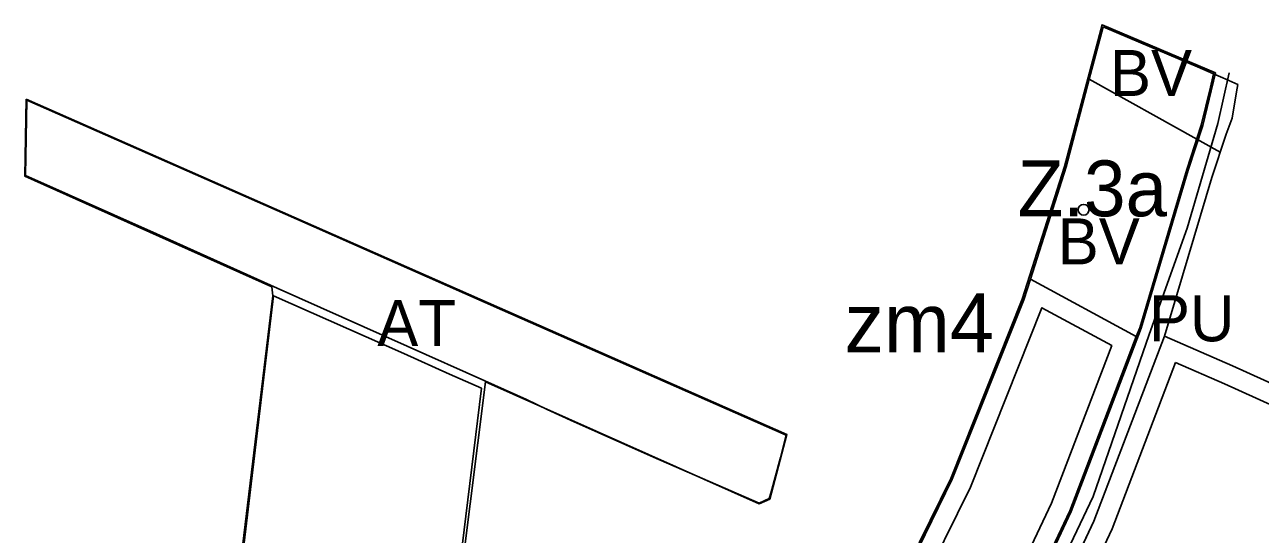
# Model space of a CAD drawing. Extents: x -555070 to -553076, y -1186731 to -1182766.
# Drawn here: x -555035.2 to -554659.4, y -1185196 to -1185040.9 of the extents above; entities that cross this region are included whole.
import ezdxf

# ---------------------------------------------------------------- set-up
doc = ezdxf.new("R2010")
doc.units = 0
for name, color, linetype in [('HRANICE_ZMENY_DO_KOO', 7, 'Continuous'), ('Level 10', 7, 'Continuous'), ('Level 13', 7, 'Continuous'), ('Level 4', 7, 'Continuous'), ('Level 46', 7, 'Continuous'), ('Level 52', 7, 'Continuous'), ('Level 56', 7, 'Continuous'), ('Level 59', 7, 'Continuous'), ('Level 6', 7, 'Continuous'), ('Level 63', 7, 'Continuous'), ('navrh_BV', 7, 'Continuous'), ('OBRYS_PLOCH', 7, 'Continuous'), ('rezerva_BV', 7, 'Continuous'), ('stav_AT', 7, 'Continuous'), ('stav_BV', 7, 'Continuous'), ('stav_PU', 7, 'Continuous'), ('ZU_plocha_aktualizace', 7, 'Continuous')]:
    doc.layers.add(name, color=color, linetype=linetype)

msp = doc.modelspace()

# ---------------------------------------------------------------- linework, layer by layer
at = {"layer": 'HRANICE_ZMENY_DO_KOO'}
msp.add_lwpolyline([(-554781.14, -1185319.16), (-554749.64, -1185258.53), (-554735.45, -1185228.43), (-554735.94, -1185228.17), (-554732.88, -1185222.18), (-554722.28, -1185200.47), (-554716.89, -1185189.03), (-554695.6, -1185133.26), (-554681.28, -1185085.12), (-554676.85, -1185071.58), (-554673.03, -1185055.54), (-554678.3, -1185053.24), (-554698.85, -1185044.53), (-554707.52, -1185040.87), (-554718.97, -1185084), (-554731.8, -1185124.46), (-554753.51, -1185179), (-554769.31, -1185211.12), (-554783.7, -1185241.67), (-554814.38, -1185300.72)], dxfattribs=at)
msp.add_lwpolyline([(-555034.79, -1185063.53), (-555035.23, -1185086.95), (-554960.01, -1185120.64), (-554959.71, -1185123.38), (-554985.4, -1185335.61), (-554942.05, -1185324.03), (-554915.83, -1185315.05), (-554895.09, -1185149.59), (-554811.81, -1185186.74), (-554808.6, -1185185.28), (-554803.37, -1185165.66)], close=True, dxfattribs=at)
at = {"layer": 'Level 13'}
for p, q in [((-554707.18, -1185041.55), (-554711.41, -1185057.49)), ((-554673.61, -1185055.83), (-554678.5, -1185053.7)), ((-554711.41, -1185057.49), (-554718.48, -1185084.14)), ((-554674.57, -1185059.86), (-554673.61, -1185055.83)), ((-554677.33, -1185071.44), (-554674.57, -1185059.86)), ((-554678.65, -1185075.47), (-554677.33, -1185071.44)), ((-554681.76, -1185084.97), (-554679.31, -1185077.48)), ((-554679.31, -1185077.48), (-554678.73, -1185075.72)), ((-554678.73, -1185075.72), (-554678.65, -1185075.47)), ((-554718.48, -1185084.14), (-554729.32, -1185118.29)), ((-554696.07, -1185133.1), (-554681.76, -1185084.97)), ((-554729.32, -1185118.29), (-554731.33, -1185124.63)), ((-554731.33, -1185124.63), (-554753.06, -1185179.2)), ((-554697.1, -1185135.79), (-554696.07, -1185133.1)), ((-554717.35, -1185188.83), (-554697.1, -1185135.79)), ((-554688.49, -1185135.67), (-554709.98, -1185191.97)), ((-554667.86, -1185144.71), (-554688.49, -1185135.67)), ((-554652.87, -1185151.49), (-554667.86, -1185144.71)), ((-554753.06, -1185179.2), (-554768.86, -1185211.34)), ((-554722.73, -1185200.26), (-554717.35, -1185188.83)), ((-554709.98, -1185191.97), (-554738.91, -1185253.34))]:
    msp.add_line(p, q, dxfattribs=at)
msp.add_lwpolyline([(-554678.5, -1185053.7), (-554699.04, -1185044.99), (-554707.18, -1185041.55)], dxfattribs=at)
at = {"layer": 'Level 4'}
msp.add_circle((-554713.12, -1185097.19), 1.64, dxfattribs=at)
at = {"layer": 'Level 52'}
msp.add_lwpolyline([(-554707.18, -1185041.55), (-554711.41, -1185057.49), (-554678.73, -1185075.72), (-554671.61, -1185079.7)], dxfattribs=at)
at = {"layer": 'Level 56'}
for p, q in [((-554711.41, -1185057.49), (-554718.48, -1185084.14)), ((-554711.41, -1185057.49), (-554678.73, -1185075.72)), ((-554681.76, -1185084.97), (-554679.31, -1185077.48)), ((-554679.31, -1185077.48), (-554678.65, -1185075.47)), ((-554718.48, -1185084.14), (-554729.32, -1185118.29)), ((-554696.07, -1185133.1), (-554681.76, -1185084.97)), ((-554729.32, -1185118.29), (-554697.1, -1185135.79)), ((-554697.1, -1185135.79), (-554696.07, -1185133.1))]:
    msp.add_line(p, q, dxfattribs=at)
at = {"layer": 'Level 6'}
msp.add_lwpolyline([(-554731.38, -1185228.54), (-554728.11, -1185222.01), (-554710.22, -1185184.49), (-554693.2, -1185135.17), (-554681.62, -1185102.76), (-554672.29, -1185070.96), (-554668.89, -1185055.54)], dxfattribs=at)
at = {"layer": 'navrh_BV'}
for p, q in [((-554711.41, -1185057.49), (-554718.48, -1185084.14)), ((-554678.73, -1185075.72), (-554711.41, -1185057.49)), ((-554681.76, -1185084.97), (-554679.31, -1185077.48)), ((-554679.31, -1185077.48), (-554678.73, -1185075.72)), ((-554718.48, -1185084.14), (-554729.32, -1185118.29)), ((-554696.07, -1185133.1), (-554681.76, -1185084.97)), ((-554729.32, -1185118.29), (-554697.1, -1185135.79)), ((-554697.1, -1185135.79), (-554696.07, -1185133.1))]:
    msp.add_line(p, q, dxfattribs=at)
at = {"layer": 'OBRYS_PLOCH'}
for p, q in [((-554707.18, -1185041.55), (-554711.41, -1185057.49)), ((-554673.61, -1185055.83), (-554678.5, -1185053.7)), ((-554711.41, -1185057.49), (-554678.73, -1185075.72)), ((-554673.61, -1185055.83), (-554674.57, -1185059.86)), ((-554674.57, -1185059.86), (-554673.61, -1185055.83)), ((-554670.81, -1185057.05), (-554673.61, -1185055.83)), ((-554670.81, -1185057.05), (-554673.61, -1185055.83)), ((-554666.18, -1185059.07), (-554670.81, -1185057.05)), ((-554666.18, -1185059.07), (-554670.81, -1185057.05)), ((-554674.57, -1185059.86), (-554677.33, -1185071.44)), ((-554677.33, -1185071.44), (-554674.57, -1185059.86)), ((-554667.89, -1185069.33), (-554666.61, -1185061.26)), ((-554666.61, -1185061.26), (-554666.18, -1185059.07)), ((-554666.61, -1185061.26), (-554666.18, -1185059.07)), ((-554669.8, -1185074.16), (-554667.89, -1185069.33)), ((-554677.33, -1185071.44), (-554679.31, -1185077.48)), ((-554677.33, -1185071.44), (-554679.31, -1185077.48)), ((-554678.65, -1185075.47), (-554677.33, -1185071.44)), ((-554679.31, -1185077.48), (-554681.76, -1185084.97)), ((-554679.31, -1185077.48), (-554681.76, -1185084.97)), ((-554678.73, -1185075.72), (-554678.65, -1185075.47)), ((-554674.12, -1185087.36), (-554669.8, -1185074.16)), ((-554674.12, -1185087.36), (-554669.8, -1185074.16)), ((-554681.76, -1185084.97), (-554696.07, -1185133.1)), ((-554681.76, -1185084.97), (-554696.07, -1185133.1)), ((-554688.49, -1185135.67), (-554674.12, -1185087.36)), ((-554688.49, -1185135.67), (-554674.12, -1185087.36)), ((-554959.51, -1185123.38), (-554968.49, -1185198.61)), ((-554919.89, -1185140.98), (-554959.51, -1185123.38)), ((-554696.07, -1185133.1), (-554717.35, -1185188.83)), ((-554696.07, -1185133.1), (-554717.35, -1185188.83)), ((-554709.98, -1185191.97), (-554688.49, -1185135.67)), ((-554709.98, -1185191.97), (-554688.49, -1185135.67)), ((-554905.97, -1185147.2), (-554919.89, -1185140.98)), ((-554896.25, -1185151.54), (-554905.97, -1185147.2)), ((-554905.64, -1185227.88), (-554896.25, -1185151.54)), ((-554717.35, -1185188.83), (-554722.73, -1185200.26)), ((-554717.35, -1185188.83), (-554722.73, -1185200.26)), ((-554738.91, -1185253.34), (-554709.98, -1185191.97)), ((-554738.91, -1185253.34), (-554709.98, -1185191.97))]:
    msp.add_line(p, q, dxfattribs=at)
for points in [[(-554678.5, -1185053.7), (-554699.04, -1185044.99), (-554707.18, -1185041.55)], [(-554673.61, -1185055.83), (-554674.57, -1185059.86), (-554677.33, -1185071.44)], [(-554669.8, -1185074.16), (-554667.89, -1185069.33), (-554666.61, -1185061.26)]]:
    msp.add_lwpolyline(points, dxfattribs=at)
at = {"layer": 'rezerva_BV'}
for p, q in [((-554729.32, -1185118.29), (-554731.33, -1185124.63)), ((-554729.32, -1185118.29), (-554731.33, -1185124.63)), ((-554697.1, -1185135.79), (-554729.32, -1185118.29)), ((-554697.1, -1185135.79), (-554729.32, -1185118.29)), ((-554731.33, -1185124.63), (-554753.06, -1185179.2)), ((-554731.33, -1185124.63), (-554753.06, -1185179.2)), ((-554717.35, -1185188.83), (-554697.1, -1185135.79)), ((-554717.35, -1185188.83), (-554697.1, -1185135.79)), ((-554688.49, -1185135.67), (-554709.98, -1185191.97)), ((-554688.49, -1185135.67), (-554709.98, -1185191.97)), ((-554667.86, -1185144.71), (-554688.49, -1185135.67)), ((-554667.86, -1185144.71), (-554688.49, -1185135.67)), ((-554704.46, -1185194.32), (-554685.13, -1185143.69)), ((-554685.13, -1185143.69), (-554670.3, -1185150.19)), ((-554652.87, -1185151.49), (-554667.86, -1185144.71)), ((-554652.87, -1185151.49), (-554667.86, -1185144.71)), ((-554670.3, -1185150.19), (-554655.3, -1185156.98)), ((-554753.06, -1185179.2), (-554768.86, -1185211.34)), ((-554753.06, -1185179.2), (-554768.86, -1185211.34)), ((-554722.73, -1185200.26), (-554717.35, -1185188.83)), ((-554722.73, -1185200.26), (-554717.35, -1185188.83)), ((-554709.98, -1185191.97), (-554738.91, -1185253.34)), ((-554709.98, -1185191.97), (-554738.91, -1185253.34))]:
    msp.add_line(p, q, dxfattribs=at)
for points in [[(-554755.47, -1185255.65), (-554783.85, -1185310.28), (-554805.8, -1185298.3), (-554777.88, -1185244.55), (-554763.45, -1185213.94), (-554747.57, -1185181.64), (-554725.82, -1185127.02), (-554704.58, -1185138.55), (-554722.87, -1185186.48), (-554728.14, -1185197.66), (-554738.8, -1185219.49), (-554741.6, -1185226.21), (-554755.47, -1185255.65)], [(-554766.29, -1185319.86), (-554737.54, -1185264.52), (-554704.46, -1185194.32)]]:
    msp.add_lwpolyline(points, dxfattribs=at)
at = {"layer": 'stav_AT'}
for p, q in [((-554959.51, -1185123.38), (-554968.49, -1185198.61)), ((-554919.89, -1185140.98), (-554959.51, -1185123.38)), ((-554905.97, -1185147.2), (-554919.89, -1185140.98)), ((-554896.25, -1185151.54), (-554905.97, -1185147.2)), ((-554905.64, -1185227.88), (-554896.25, -1185151.54))]:
    msp.add_line(p, q, dxfattribs=at)
for points in [[(-555034.6, -1185063.83), (-555035.03, -1185086.82), (-554995.14, -1185104.5), (-554958.47, -1185121.11), (-554918.85, -1185138.71), (-554895.25, -1185149.3), (-554882.6, -1185154.99), (-554876.27, -1185158.01), (-554869.18, -1185161.26), (-554843.98, -1185172.48)], [(-554952.46, -1185100.05), (-555034.6, -1185063.83)], [(-554889.9, -1185127.79), (-554952.46, -1185100.05)], [(-554843.98, -1185172.48), (-554811.81, -1185186.52), (-554808.77, -1185185.14), (-554808.23, -1185183.43), (-554805.28, -1185172.63), (-554803.61, -1185165.77), (-554866.89, -1185137.92), (-554889.9, -1185127.79)]]:
    msp.add_lwpolyline(points, dxfattribs=at)
at = {"layer": 'stav_BV'}
for p, q in [((-554707.18, -1185041.55), (-554711.41, -1185057.49)), ((-554673.61, -1185055.83), (-554678.5, -1185053.7)), ((-554711.41, -1185057.49), (-554678.73, -1185075.72)), ((-554674.57, -1185059.86), (-554673.61, -1185055.83)), ((-554677.33, -1185071.44), (-554674.57, -1185059.86)), ((-554678.65, -1185075.47), (-554677.33, -1185071.44)), ((-554678.73, -1185075.72), (-554678.65, -1185075.47))]:
    msp.add_line(p, q, dxfattribs=at)
msp.add_lwpolyline([(-554678.5, -1185053.7), (-554699.04, -1185044.99), (-554707.18, -1185041.55)], dxfattribs=at)
at = {"layer": 'stav_PU'}
for p, q in [((-554673.61, -1185055.83), (-554674.57, -1185059.86)), ((-554670.81, -1185057.05), (-554673.61, -1185055.83)), ((-554670.81, -1185057.05), (-554673.61, -1185055.83)), ((-554666.18, -1185059.07), (-554670.81, -1185057.05)), ((-554666.18, -1185059.07), (-554670.81, -1185057.05)), ((-554674.57, -1185059.86), (-554677.33, -1185071.44)), ((-554666.61, -1185061.26), (-554666.18, -1185059.07)), ((-554666.61, -1185061.26), (-554666.18, -1185059.07)), ((-554677.33, -1185071.44), (-554679.31, -1185077.48)), ((-554679.31, -1185077.48), (-554681.76, -1185084.97)), ((-554679.31, -1185077.48), (-554681.76, -1185084.97)), ((-554674.12, -1185087.36), (-554669.8, -1185074.16)), ((-554674.12, -1185087.36), (-554669.8, -1185074.16)), ((-554681.76, -1185084.97), (-554696.07, -1185133.1)), ((-554688.49, -1185135.67), (-554674.12, -1185087.36)), ((-554688.49, -1185135.67), (-554674.12, -1185087.36)), ((-554696.07, -1185133.1), (-554717.35, -1185188.83)), ((-554709.98, -1185191.97), (-554688.49, -1185135.67)), ((-554717.35, -1185188.83), (-554722.73, -1185200.26)), ((-554717.35, -1185188.83), (-554722.73, -1185200.26)), ((-554738.91, -1185253.34), (-554709.98, -1185191.97))]:
    msp.add_line(p, q, dxfattribs=at)
for points in [[(-554673.61, -1185055.83), (-554674.57, -1185059.86), (-554677.33, -1185071.44), (-554679.31, -1185077.48)], [(-554669.8, -1185074.16), (-554667.89, -1185069.33), (-554666.61, -1185061.26)], [(-554669.8, -1185074.16), (-554667.89, -1185069.33), (-554666.61, -1185061.26)], [(-554681.76, -1185084.97), (-554696.07, -1185133.1), (-554717.35, -1185188.83)], [(-554738.91, -1185253.34), (-554709.98, -1185191.97), (-554688.49, -1185135.67)]]:
    msp.add_lwpolyline(points, dxfattribs=at)
at = {"layer": 'ZU_plocha_aktualizace'}
for p, q in [((-554707.18, -1185041.55), (-554711.41, -1185057.49)), ((-554707.18, -1185041.55), (-554711.41, -1185057.49)), ((-554673.61, -1185055.83), (-554678.5, -1185053.7)), ((-554673.61, -1185055.83), (-554678.5, -1185053.7)), ((-554711.41, -1185057.49), (-554678.73, -1185075.72)), ((-554711.41, -1185057.49), (-554678.73, -1185075.72)), ((-554674.57, -1185059.86), (-554673.61, -1185055.83)), ((-554673.61, -1185055.83), (-554674.57, -1185059.86)), ((-554674.57, -1185059.86), (-554673.61, -1185055.83)), ((-554673.61, -1185055.83), (-554674.57, -1185059.86)), ((-554670.81, -1185057.05), (-554673.61, -1185055.83)), ((-554670.81, -1185057.05), (-554673.61, -1185055.83)), ((-554666.18, -1185059.07), (-554670.81, -1185057.05)), ((-554666.18, -1185059.07), (-554670.81, -1185057.05)), ((-554677.33, -1185071.44), (-554674.57, -1185059.86)), ((-554674.57, -1185059.86), (-554677.33, -1185071.44)), ((-554677.33, -1185071.44), (-554674.57, -1185059.86)), ((-554674.57, -1185059.86), (-554677.33, -1185071.44)), ((-554667.89, -1185069.33), (-554666.61, -1185061.26)), ((-554666.61, -1185061.26), (-554666.18, -1185059.07)), ((-554666.61, -1185061.26), (-554666.18, -1185059.07)), ((-554669.8, -1185074.16), (-554667.89, -1185069.33)), ((-554678.65, -1185075.47), (-554677.33, -1185071.44)), ((-554677.33, -1185071.44), (-554678.65, -1185075.47)), ((-554678.65, -1185075.47), (-554677.33, -1185071.44)), ((-554677.33, -1185071.44), (-554678.65, -1185075.47)), ((-554678.73, -1185075.72), (-554678.65, -1185075.47)), ((-554678.65, -1185075.47), (-554678.73, -1185075.72)), ((-554678.73, -1185075.72), (-554678.65, -1185075.47)), ((-554678.65, -1185075.47), (-554678.73, -1185075.72)), ((-554678.73, -1185075.72), (-554671.61, -1185079.7)), ((-554678.73, -1185075.72), (-554671.61, -1185079.7)), ((-554671.61, -1185079.7), (-554669.8, -1185074.16)), ((-554671.61, -1185079.7), (-554669.8, -1185074.16))]:
    msp.add_line(p, q, dxfattribs=at)
for points in [[(-554678.5, -1185053.7), (-554699.04, -1185044.99), (-554707.18, -1185041.55)], [(-554678.5, -1185053.7), (-554699.04, -1185044.99), (-554707.18, -1185041.55)], [(-554669.8, -1185074.16), (-554667.89, -1185069.33), (-554666.61, -1185061.26)]]:
    msp.add_lwpolyline(points, dxfattribs=at)

# ---------------------------------------------------------------- texts
at = {"layer": 'Level 10'}
msp.add_text('zm4', height=18, dxfattribs=at).set_placement((-554785.89, -1185140.63))
at = {"layer": 'Level 46'}
msp.add_text('Z.3a', height=17, dxfattribs=at).set_placement((-554733.21, -1185099.19))
at = {"layer": 'Level 59'}
for s, p in [('BV', (-554705.11, -1185062.57)), ('AT', (-554927.98, -1185138.71)), ('PU', (-554693.25, -1185137.24))]:
    msp.add_text(s, height=14, dxfattribs=at).set_placement(p)
at = {"layer": 'Level 63'}
msp.add_text('BV', height=14, dxfattribs=at).set_placement((-554721, -1185113.82))

doc.saveas('drawing.dxf')
